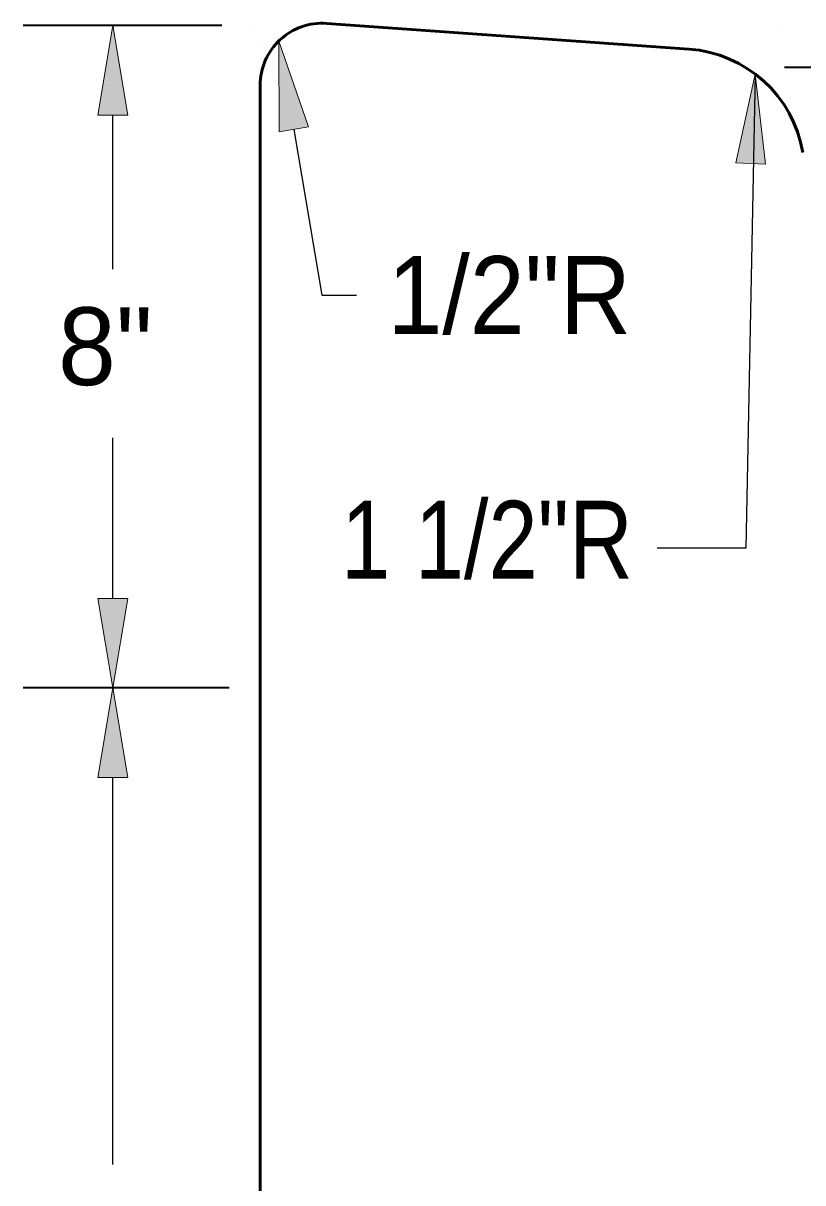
# Model space of a CAD drawing. Extents: x 36.6 to 71.9, y 0.8 to 22.8.
# Drawn here: x 55.394 to 56.961, y 18.022 to 20.351 of the extents above; entities that cross this region are included whole.
import ezdxf

# ---------------------------------------------------------------- set-up
doc = ezdxf.new("R2010")
doc.units = 0
doc.header["$LTSCALE"] = 0.062
for name, color, linetype, lineweight in [('1', 7, 'Continuous', 13), ('3', 7, 'Continuous', 25), ('8', 7, 'Continuous', 13)]:
    doc.layers.add(name, color=color, linetype=linetype, lineweight=lineweight)

msp = doc.modelspace()

# ---------------------------------------------------------------- hatches: boundary and pattern name
at = {"layer": '1'}
for points in [[(55.60425, 20.16633), (55.54425, 20.16633), (55.57425, 20.34633), (55.57425, 20.34633)], [(55.60425, 19.196), (55.54425, 19.196), (55.57425, 19.016), (55.57425, 19.016)], [(55.60425, 18.836), (55.54425, 18.836), (55.57425, 19.016), (55.57425, 19.016)]]:
    msp.add_hatch(color=256, dxfattribs=at).paths.add_polyline_path(points)
at = {"layer": '3'}
for points in [[(55.90825, 20.13283), (55.96742, 20.143), (55.90758, 20.31533), (55.90758, 20.31533)], [(56.82575, 20.07092), (56.88575, 20.06792), (56.86492, 20.24917), (56.86492, 20.24917)]]:
    msp.add_hatch(color=256, dxfattribs=at).paths.add_polyline_path(points)

# ---------------------------------------------------------------- linework, layer by layer
at = {"layer": '1', "lineweight": 35}
for p, q in [((55.79333, 20.34633), (55.39425, 20.34633)), ((56.92408, 20.26308), (57.7005, 20.26308)), ((55.80775, 19.016), (55.39425, 19.016))]:
    msp.add_line(p, q, dxfattribs=at)
at = {"layer": '1', "lineweight": 53}
for p, q in [((56.00408, 20.35092), (56.73183, 20.29917)), ((55.87025, 16.68067), (55.87025, 20.22625))]:
    msp.add_line(p, q, dxfattribs=at)
at = {"layer": '1', "lineweight": 25}
for p, q in [((55.57425, 19.85717), (55.57425, 20.16633)), ((55.57425, 19.196), (55.57425, 19.51858)), ((55.57425, 18.05875), (55.57425, 18.836))]:
    msp.add_line(p, q, dxfattribs=at)
at = {"layer": '1'}
msp.add_line((55.63675, 19.016), (55.75425, 19.016), dxfattribs=at)
for points in [[(55.60425, 20.16633), (55.54425, 20.16633), (55.57425, 20.34633), (55.57425, 20.34633)], [(55.60425, 19.196), (55.54425, 19.196), (55.57425, 19.016), (55.57425, 19.016)], [(55.60425, 18.836), (55.54425, 18.836), (55.57425, 19.016), (55.57425, 19.016)]]:
    msp.add_lwpolyline(points, close=True, dxfattribs=at)
at = {"layer": '1', "lineweight": 53}
for centre, radius, start, end in [((55.99525, 20.22625), 0.125, 85.93242, 180), ((56.71408, 20.04983), 0.25, 9.6122, 85.93242)]:
    msp.add_arc(centre, radius, start, end, dxfattribs=at)
at = {"layer": '3', "lineweight": 13}
for points in [[(55.90825, 20.13283), (55.96742, 20.143), (55.90758, 20.31533), (55.90758, 20.31533)], [(56.82575, 20.07092), (56.88575, 20.06792), (56.86492, 20.24917), (56.86492, 20.24917)]]:
    msp.add_lwpolyline(points, close=True, dxfattribs=at)
at = {"layer": '3'}
for points in [[(56.86492, 20.24917), (56.84592, 19.29675), (56.668, 19.29675)], [(55.93783, 20.13792), (55.99458, 19.80525), (56.06392, 19.80525)]]:
    msp.add_lwpolyline(points, dxfattribs=at)
at = {"layer": '8'}
for p, q in [((55.57425, 20.34633), (55.57433, 20.34633)), ((55.85583, 20.34633), (55.85592, 20.34633)), ((56.917, 20.33933), (56.91708, 20.33933)), ((55.86967, 20.31158), (55.86975, 20.31158)), ((56.86158, 20.26308), (56.86167, 20.26308)), ((55.57425, 19.016), (55.57433, 19.016)), ((55.57425, 19.016), (55.57433, 19.016)), ((55.87025, 19.016), (55.87033, 19.016))]:
    msp.add_line(p, q, dxfattribs=at)

# ---------------------------------------------------------------- texts
at = {"layer": '1'}
msp.add_text('8"', height=0.1562, dxfattribs=at).set_placement((55.46425, 19.62433))
at = {"layer": '3'}
for s, width, p in [('1/2"R', 0.95, (56.126, 19.72717)), ('1 1/2"R', 0.85, (56.03292, 19.23575))]:
    msp.add_text(s, height=0.1562, dxfattribs=dict(at, width=width)).set_placement(p)

doc.saveas('drawing.dxf')
